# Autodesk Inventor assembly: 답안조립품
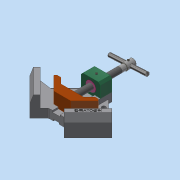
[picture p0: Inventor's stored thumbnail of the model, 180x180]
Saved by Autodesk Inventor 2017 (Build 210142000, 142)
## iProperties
Part Number: 답안조립품
Material: 일반
Document SubType Name: Assembly
Designer: 222
Author: 222
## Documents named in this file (11)
- C:\Users\222\Desktop\700506V1054\답안조립품.iam
- C:\Users\222\Desktop\700506V1054\본체.ipt
- C:\Users\222\Desktop\700506V1054\리드스크류.ipt
- C:\Users\222\Desktop\700506V1054\멈춤나사 M4x5.ipt
- C:\Users\222\Desktop\700506V1054\멈춤나사 M4x10.ipt
- C:\Users\222\Desktop\700506V1054\볼트 M4x16.ipt
- C:\Users\222\Desktop\700506V1054\부시.ipt
- C:\Users\222\Desktop\700506V1054\서포트.ipt
- C:\Users\222\Desktop\700506V1054\조.ipt
- C:\Users\222\Desktop\700506V1054\평행 핀 2.5x24.ipt
- C:\Users\222\Desktop\700506V1054\핸들.ipt
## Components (1 placed, 1 different names)
1. 핸들:1
